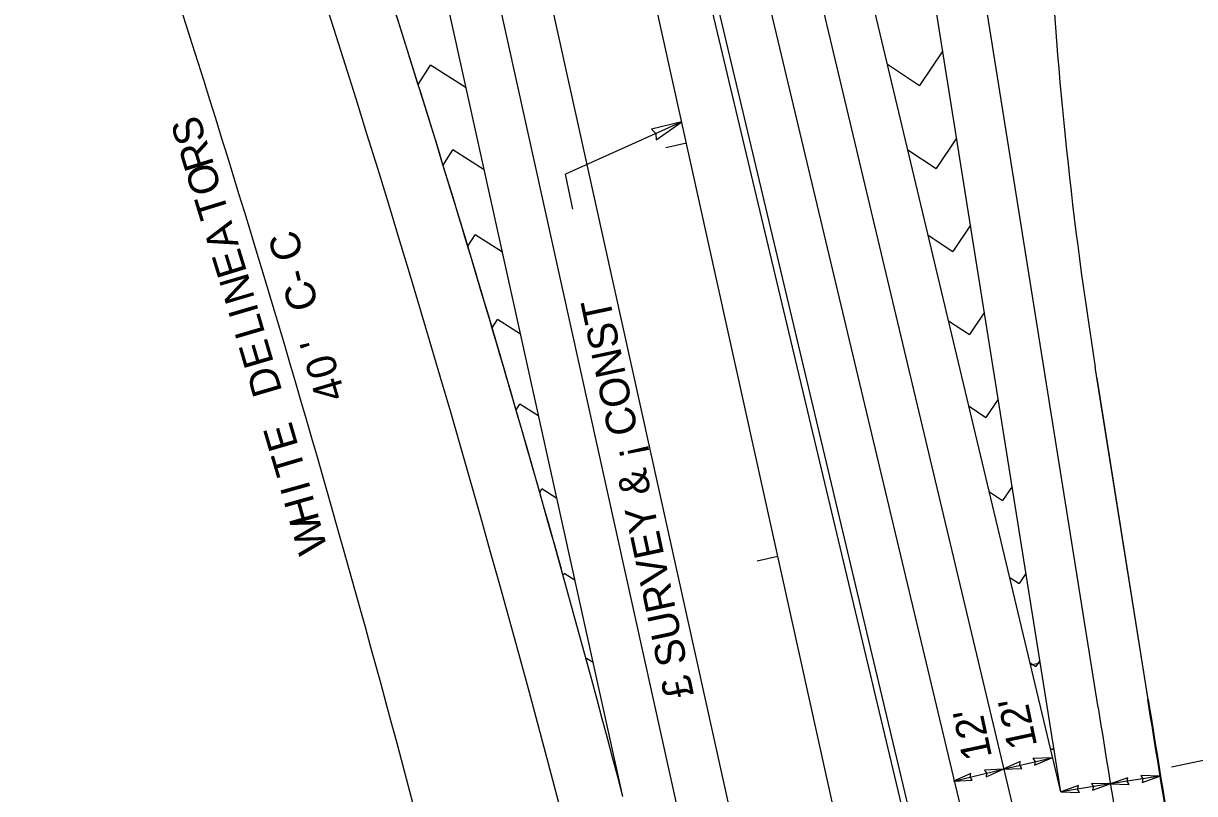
# Model space of a CAD drawing. Extents: x 578088 to 579220, y 1508751 to 1510400.
# Drawn here: x 578418.2 to 578695, y 1509206 to 1509387.9 of the extents above; entities that cross this region are included whole.
import ezdxf

# ---------------------------------------------------------------- set-up
doc = ezdxf.new("R2010")
doc.units = 0
for name, color, linetype in [('1', 7, 'Continuous'), ('18', 7, 'Continuous'), ('2', 7, 'Continuous'), ('28', 7, 'Continuous'), ('41', 7, 'Continuous'), ('46', 7, 'Continuous'), ('52', 7, 'Continuous'), ('8', 7, 'Continuous')]:
    doc.layers.add(name, color=color, linetype=linetype)

msp = doc.modelspace()

# ---------------------------------------------------------------- linework, layer by layer
at = {"layer": '1'}
for p, q in [((578639.69, 1509066.69), (578362.17, 1510321.74)), ((578559.88, 1509205.29), (578315.3, 1510311.37))]:
    msp.add_line(p, q, dxfattribs=at)
at = {"layer": '18'}
for p, q in [((578659.48, 1508810.53), (578375.62, 1510094.27)), ((578663.47, 1509155.01), (578558.43, 1509596.29)), ((578672.16, 1509226.28), (578643.76, 1509404.4)), ((578663.36, 1509206.35), (578632.08, 1509402.54)), ((578663.36, 1509206.35), (578617.48, 1509399.06)), ((578635.45, 1509381.4), (578629.99, 1509373.22)), ((578622.43, 1509378.26), (578629.99, 1509373.22)), ((578511.53, 1509373.44), (578514.44, 1509378.03)), ((578522.86, 1509372.7), (578514.44, 1509378.03)), ((578638.73, 1509360.83), (578633.91, 1509353.61)), ((578517.42, 1509354.4), (578519.7, 1509358.01)), ((578527.15, 1509353.3), (578519.7, 1509358.01)), ((578627.24, 1509358.06), (578633.91, 1509353.61)), ((578642.01, 1509340.26), (578637.83, 1509334)), ((578523.24, 1509335.26), (578524.97, 1509337.99)), ((578531.44, 1509333.9), (578524.97, 1509337.99)), ((578632.05, 1509337.86), (578637.83, 1509334)), ((578528.99, 1509315.99), (578530.24, 1509317.97)), ((578535.73, 1509314.49), (578530.24, 1509317.97)), ((578636.86, 1509317.65), (578641.76, 1509314.39)), ((578645.29, 1509319.68), (578641.76, 1509314.39)), ((578684.01, 1509228.17), (578671.91, 1509304.08)), ((578534.66, 1509296.61), (578535.5, 1509297.95)), ((578540.03, 1509295.09), (578535.5, 1509297.95)), ((578648.57, 1509299.11), (578645.68, 1509294.78)), ((578641.67, 1509297.45), (578645.68, 1509294.78)), ((578540.25, 1509277.1), (578540.77, 1509277.93)), ((578544.32, 1509275.69), (578540.77, 1509277.93)), ((578646.48, 1509277.24), (578649.6, 1509275.17)), ((578651.85, 1509278.54), (578649.6, 1509275.17)), ((578545.76, 1509257.47), (578546.04, 1509257.91)), ((578548.61, 1509256.29), (578546.04, 1509257.91)), ((578651.29, 1509257.04), (578653.52, 1509255.55)), ((578655.13, 1509257.96), (578653.52, 1509255.55)), ((578551.2, 1509237.72), (578551.31, 1509237.89)), ((578552.9, 1509236.88), (578551.31, 1509237.89)), ((578658.41, 1509237.39), (578657.44, 1509235.94)), ((578656.1, 1509236.83), (578657.44, 1509235.94)), ((578660.91, 1509216.63), (578661.36, 1509216.33)), ((578661.69, 1509216.82), (578661.36, 1509216.33))]:
    msp.add_line(p, q, dxfattribs=at)
for centre, radius, start, end in [((579629.37, 1509459.39), 969.97, 176.83826, 189.05927), ((584342.13, 1510130.3), 5741.58, 189.05897, 189.735667), ((584342.13, 1510130.3), 5729.75, 189.05897, 189.730018)]:
    msp.add_arc(centre, radius, start, end, dxfattribs=at)
at = {"layer": '2'}
for p, q in [((578651.7, 1509152.41), (578547.48, 1509590.23)), ((578656.38, 1509236.37), (578658.33, 1509236.84))]:
    msp.add_line(p, q, dxfattribs=at)
at = {"layer": '28'}
for p, q in [((578574.92, 1509359.61), (578570.04, 1509358.53)), ((578596.51, 1509261.97), (578591.63, 1509260.89))]:
    msp.add_line(p, q, dxfattribs=at)
at = {"layer": '41'}
for p, q in [((578671.2, 1508813.02), (578338.64, 1510317)), ((578684.01, 1509228.17), (578671.5, 1509306.66)), ((578684.01, 1509228.17), (578671.5, 1509306.66))]:
    msp.add_line(p, q, dxfattribs=at)
for centre, radius, start, end in [((574851.28, 1508229.92), 3819.72, 12.46859, 20.71859), ((579629.37, 1509459.39), 969.97, 176.83826, 189.05927), ((579629.37, 1509459.39), 969.97, 176.83826, 189.05927), ((574851.28, 1508229.92), 3834.72, 14.7352, 19.27173), ((584342.13, 1510130.3), 5729.58, 189.05897, 189.729939), ((584342.13, 1510130.3), 5729.58, 189.05897, 189.729939), ((584342.13, 1510130.3), 5729.58, 189.05897, 189.729939)]:
    msp.add_arc(centre, radius, start, end, dxfattribs=at)
at = {"layer": '46'}
for p, q in [((578632.73, 1509173.81), (578580.62, 1509392.73)), ((578634.19, 1509174.14), (578582.08, 1509393.05))]:
    msp.add_line(p, q, dxfattribs=at)
at = {"layer": '52'}
for p, q in [((578573.81, 1509364.63), (578546.33, 1509352.32)), ((578573.81, 1509364.63), (578566.62, 1509362.94)), ((578567.74, 1509360.44), (578573.81, 1509364.63)), ((578566.62, 1509362.94), (578567.69, 1509361.89)), ((578567.69, 1509361.89), (578567.74, 1509360.44)), ((578548.09, 1509344.04), (578546.33, 1509352.32)), ((578869.57, 1509250.44), (578689.51, 1509212.17)), ((578653.79, 1509213.49), (578649.74, 1509211.7)), ((578649.74, 1509211.7), (578661.2, 1509214.42)), ((578653.66, 1509212.63), (578653.79, 1509213.49)), ((578654.17, 1509211.89), (578653.66, 1509212.63)), ((578661.2, 1509214.42), (578656.78, 1509214.23)), ((578656.78, 1509214.23), (578657.29, 1509213.49)), ((578657.16, 1509212.63), (578661.2, 1509214.42)), ((578657.29, 1509213.49), (578657.16, 1509212.63)), ((578638.02, 1509208.9), (578649.74, 1509211.7)), ((578642.06, 1509210.7), (578638.02, 1509208.91)), ((578641.93, 1509209.84), (578642.06, 1509210.7)), ((578642.44, 1509209.09), (578641.93, 1509209.84)), ((578649.74, 1509211.7), (578645.32, 1509211.51)), ((578645.32, 1509211.51), (578645.83, 1509210.77)), ((578645.7, 1509209.9), (578649.74, 1509211.7)), ((578645.83, 1509210.77), (578645.7, 1509209.9)), ((578649.74, 1509211.7), (578654.17, 1509211.89)), ((578686.73, 1509210.08), (578675.04, 1509208.22)), ((578679.21, 1509209.7), (578675.04, 1509208.22)), ((578679.01, 1509208.85), (578679.21, 1509209.7)), ((578686.73, 1509210.08), (578682.3, 1509210.23)), ((578682.3, 1509210.23), (578682.76, 1509209.45)), ((578682.56, 1509208.6), (578686.73, 1509210.08)), ((578682.76, 1509209.45), (578682.56, 1509208.6)), ((578638.02, 1509208.91), (578642.44, 1509209.09)), ((578675.04, 1509208.22), (578663.36, 1509206.35)), ((578667.52, 1509207.84), (578663.36, 1509206.35)), ((578667.33, 1509206.99), (578667.52, 1509207.84)), ((578667.78, 1509206.21), (578667.33, 1509206.99)), ((578675.04, 1509208.22), (578670.61, 1509208.36)), ((578670.61, 1509208.36), (578671.07, 1509207.58)), ((578670.87, 1509206.73), (578675.04, 1509208.22)), ((578671.07, 1509207.58), (578670.87, 1509206.73)), ((578675.04, 1509208.22), (578679.47, 1509208.07)), ((578679.47, 1509208.07), (578679.01, 1509208.85)), ((578663.36, 1509206.35), (578667.78, 1509206.21))]:
    msp.add_line(p, q, dxfattribs=at)
msp.add_arc((574817.44, 1508227.41), 3819.72, 14.68854, 19.14283, dxfattribs=at)
at = {"layer": '8'}
msp.add_arc((574851.28, 1508229.92), 3834.72, 15.5225, 18.32289, dxfattribs=at)

# ---------------------------------------------------------------- texts
at = {"layer": '52'}
for s, rotation, p in [('S', 107.1167, (578461.48, 1509360.57)), ('R', 107.1167, (578463.38, 1509354.4)), ('O', 107.1167, (578465.16, 1509348.61)), ('T', 107.1167, (578466.9, 1509342.95)), ('A', 107.1167, (578469.17, 1509335.6)), ('C', 107.1167, (578484.6, 1509333.06)), ('E', 107.1167, (578471.14, 1509329.19)), ('N', 106.4229, (578473, 1509322.93)), ('-', 103.5467, (578486.13, 1509327.38)), ('C', 106.4229, (578488.1, 1509321.21)), ('I', 106.4229, (578473.94, 1509319.75)), ('£ SURVEY & ¡ CONST', 102, (578576.71, 1509229.26)), ('L', 106.4229, (578475.42, 1509314.71)), ('E', 106.4229, (578477.47, 1509307.77)), ("'", 106.4229, (578490.63, 1509312.61)), ('0', 106.4229, (578492.8, 1509305.27)), ('D', 106.4229, (578479.46, 1509301)), ('4', 106.4229, (578494.42, 1509299.77)), ('E', 106.4229, (578483.26, 1509288.1)), ('T', 106.4229, (578484.98, 1509282.26)), ('I', 105.7292, (578486.22, 1509277.8)), ('H', 105.7292, (578488.25, 1509270.57)), ('W', 105.7292, (578490.19, 1509263.7)), ("12'", 102, (578657.8, 1509217.28)), ("12'", 102, (578647.14, 1509214.66))]:
    msp.add_text(s, height=7, rotation=rotation, dxfattribs=at).set_placement(p)

doc.saveas('drawing.dxf')
